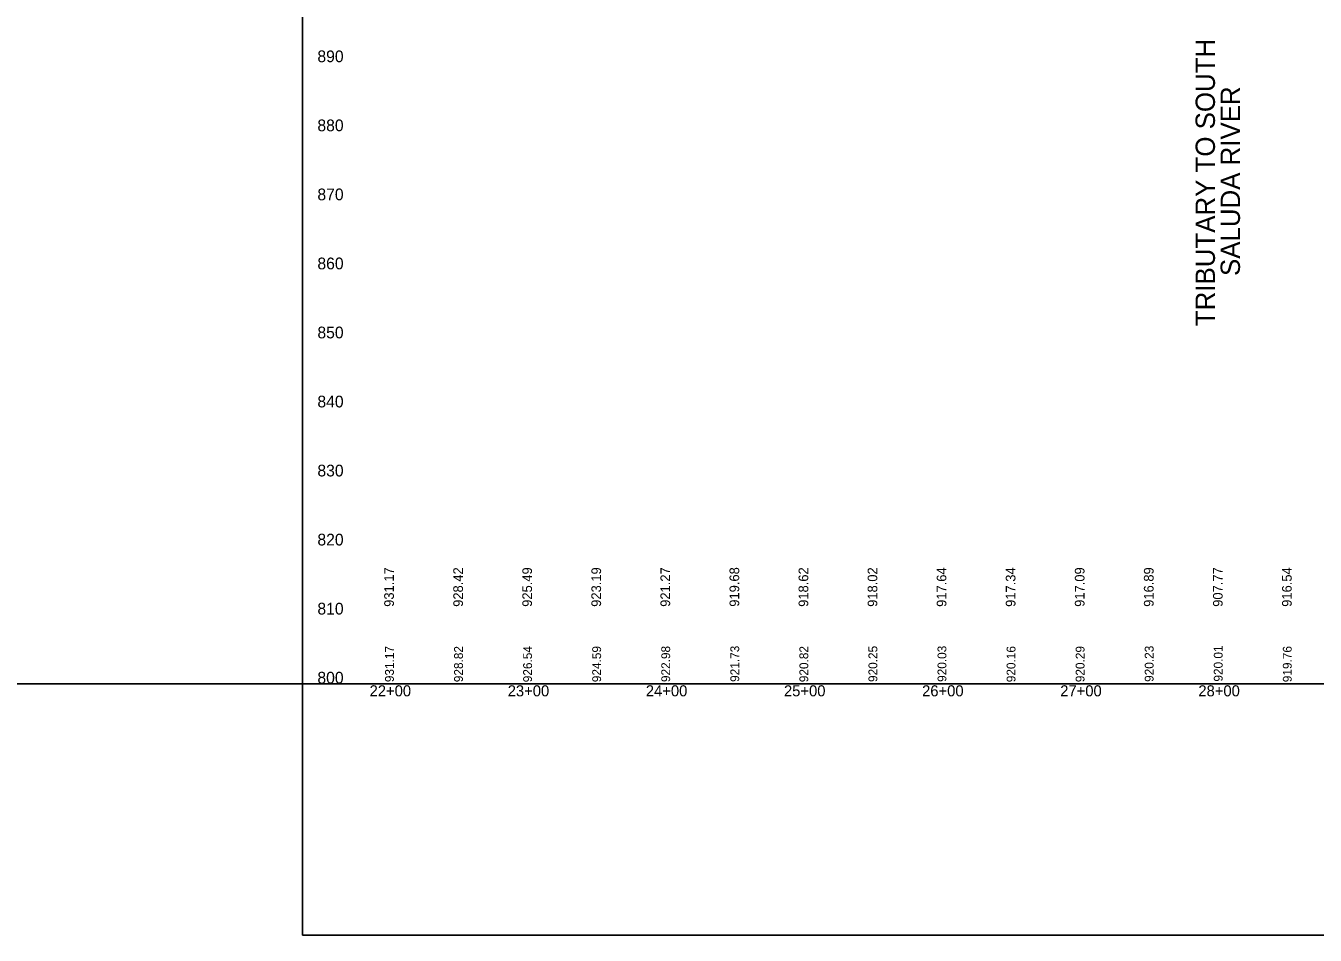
# Model space of a CAD drawing. Extents: x 1538426 to 1542651, y 1162537 to 1163637.
# Drawn here: x 1539359 to 1540293, y 1162537 to 1163195 of the extents above; entities that cross this region are included whole.
import ezdxf

# ---------------------------------------------------------------- set-up
doc = ezdxf.new("R2010")
doc.units = 0
for name, color, linetype in [('RD_DDB_ElevTX', 7, 'Continuous'), ('RD_DDB_StaTX', 7, 'Continuous'), ('RD_DDB_StripGrade', 7, 'Continuous'), ('RD_HC_Data_Tic', 7, 'Continuous'), ('RD_SHT_ShtClip', 7, 'Continuous'), ('RD_SHT_TX', 7, 'Continuous')]:
    doc.layers.add(name, color=color, linetype=linetype)

msp = doc.modelspace()

# ---------------------------------------------------------------- linework, layer by layer
at = {"layer": 'RD_HC_Data_Tic'}
msp.add_line((1538425.92, 1162718.72), (1542651.05, 1162718.72), dxfattribs=at)
at = {"layer": 'RD_SHT_ShtClip'}
for p, q in [((1539559.8, 1162536.73), (1539559.8, 1163636.73)), ((1541409.8, 1162536.73), (1539559.8, 1162536.73))]:
    msp.add_line(p, q, dxfattribs=at)

# ---------------------------------------------------------------- texts
at = {"layer": 'RD_DDB_ElevTX'}
for s, p in [('890', (1539570.55, 1163168.97)), ('880', (1539570.55, 1163118.97)), ('870', (1539570.55, 1163068.97)), ('860', (1539570.55, 1163018.97)), ('850', (1539570.55, 1162968.97)), ('840', (1539570.55, 1162918.97)), ('830', (1539570.55, 1162868.97)), ('820', (1539570.55, 1162818.97)), ('810', (1539570.55, 1162768.97)), ('800', (1539570.55, 1162718.97))]:
    msp.add_text(s, height=8.5, dxfattribs=at).set_placement(p)
at = {"layer": 'RD_DDB_StaTX'}
for s, p in [('22+00', (1539608.33, 1162709.72)), ('23+00', (1539708.33, 1162709.72)), ('24+00', (1539808.33, 1162709.72)), ('25+00', (1539908.33, 1162709.72)), ('26+00', (1540008.33, 1162709.72)), ('27+00', (1540108.33, 1162709.72)), ('28+00', (1540208.33, 1162709.72))]:
    msp.add_text(s, height=8, dxfattribs=at).set_placement(p)
at = {"layer": 'RD_DDB_StripGrade'}
for s, height, p in [('931.17', 7, (1539625.92, 1162774.54)), ('928.42', 7, (1539675.92, 1162774.54)), ('925.49', 7, (1539725.92, 1162774.55)), ('923.19', 7, (1539775.92, 1162774.55)), ('921.27', 7, (1539825.92, 1162774.56)), ('919.68', 7, (1539875.92, 1162774.62)), ('918.62', 7, (1539925.92, 1162774.54)), ('918.02', 7, (1539975.92, 1162774.54)), ('917.64', 7, (1540025.92, 1162774.5)), ('917.34', 7, (1540075.92, 1162774.5)), ('917.09', 7, (1540125.92, 1162774.55)), ('916.89', 7, (1540175.92, 1162774.55)), ('907.77', 7, (1540225.92, 1162774.56)), ('916.54', 7, (1540275.92, 1162774.56)), ('931.17', 6.4, (1539625.92, 1162720)), ('928.82', 6.4, (1539675.92, 1162719.98)), ('926.54', 6.4, (1539725.92, 1162719.94)), ('924.59', 6.4, (1539775.92, 1162719.98)), ('922.98', 6.4, (1539825.92, 1162720.06)), ('921.73', 6.4, (1539875.92, 1162720.2)), ('920.82', 6.4, (1539925.92, 1162719.98)), ('920.25', 6.4, (1539975.92, 1162720.11)), ('920.03', 6.4, (1540025.92, 1162720.2)), ('920.16', 6.4, (1540075.92, 1162719.96)), ('920.29', 6.4, (1540125.92, 1162719.98)), ('920.23', 6.4, (1540175.92, 1162720.2)), ('920.01', 6.4, (1540225.92, 1162720.41)), ('919.76', 6.4, (1540275.92, 1162719.96))]:
    msp.add_text(s, height=height, rotation=90, dxfattribs=at).set_placement(p)
at = {"layer": 'RD_SHT_TX'}
for s, p in [('TRIBUTARY TO SOUTH ', (1540220.35, 1162977.85)), ('SALUDA RIVER', (1540238.47, 1163014.13))]:
    msp.add_text(s, height=14, rotation=90, dxfattribs=at).set_placement(p)

doc.saveas('drawing.dxf')
